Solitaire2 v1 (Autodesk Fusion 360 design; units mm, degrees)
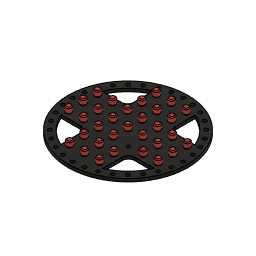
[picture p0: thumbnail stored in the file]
sketch "Esquisse" plane through (0, 0, 0) normal (0, 1, 0) x axis (1, 0, 0)
  line L1 (-45, -34.2237) -> (-77.8058, -34.2237)
  line L2 (-35, -77.4597) -> (-35, -44.2237)
  line L3 (45, -34.2237) -> (77.8058, -34.2237)
  line L4 (35, -77.4597) -> (35, -44.2237)
  line L5 (35, 44.1263) -> (35, 77.4597)
  line L6 (77.8485, 34.1263) -> (45, 34.1263)
  line L7 (-45, 34.1263) -> (-77.8485, 34.1263)
  line L8 (-35, 77.4597) -> (-35, 44.1263)
  circle C1 centre (0, 0) radius 100
  circle C2 centre (0, 0) radius 95
  circle C3 centre (0, 0) radius 89.5
  circle C4 centre (0, 0) radius 85
  circle C5 centre (0, 92.5) radius 3
  circle C6 centre (-18.0459, 90.7226) radius 3
  circle C7 centre (-35.3982, 85.4589) radius 3
  circle C8 centre (-51.3902, 76.9109) radius 3
  circle C9 centre (-65.4074, 65.4074) radius 3
  circle C10 centre (-76.9109, 51.3902) radius 3
  circle C11 centre (-85.4589, 35.3982) radius 3
  circle C12 centre (-90.7226, 18.0459) radius 3
  circle C13 centre (-92.5, 0) radius 3
  circle C14 centre (-90.7226, -18.0459) radius 3
  circle C15 centre (-85.4589, -35.3982) radius 3
  circle C16 centre (-76.9109, -51.3902) radius 3
  circle C17 centre (-65.4074, -65.4074) radius 3
  circle C18 centre (-51.3902, -76.9109) radius 3
  circle C19 centre (-35.3982, -85.4589) radius 3
  circle C20 centre (-18.0459, -90.7226) radius 3
  circle C21 centre (0, -92.5) radius 3
  circle C22 centre (18.0459, -90.7226) radius 3
  circle C23 centre (35.3982, -85.4589) radius 3
  circle C24 centre (51.3902, -76.9109) radius 3
  circle C25 centre (65.4074, -65.4074) radius 3
  circle C26 centre (76.9109, -51.3902) radius 3
  circle C27 centre (85.4589, -35.3982) radius 3
  circle C28 centre (90.7226, -18.0459) radius 3
  circle C29 centre (92.5, 0) radius 3
  circle C30 centre (90.7226, 18.0459) radius 3
  circle C31 centre (85.4589, 35.3982) radius 3
  circle C32 centre (76.9109, 51.3902) radius 3
  circle C33 centre (65.4074, 65.4074) radius 3
  circle C34 centre (51.3902, 76.9109) radius 3
  circle C35 centre (35.3982, 85.4589) radius 3
  circle C36 centre (18.0459, 90.7226) radius 3
  circle C37 centre (-25, 72.4597) radius 2.5
  circle C38 centre (0, 72.4597) radius 2.5
  circle C39 centre (25, 72.4597) radius 2.5
  circle C40 centre (-25, 48.293) radius 2.5
  circle C41 centre (0, 48.293) radius 2.5
  circle C42 centre (25, 48.293) radius 2.5
  circle C43 centre (-25, 24.1263) radius 2.5
  circle C44 centre (0, 24.1263) radius 2.5
  circle C45 centre (25, 24.1263) radius 2.5
  circle C46 centre (-25, -0.0403) radius 2.5
  circle C47 centre (0, -0.0403) radius 2.5
  circle C48 centre (25, -0.0403) radius 2.5
  circle C49 centre (-25, -24.207) radius 2.5
  circle C50 centre (0, -24.207) radius 2.5
  circle C51 centre (25, -24.207) radius 2.5
  circle C52 centre (-25, -48.3737) radius 2.5
  circle C53 centre (0, -48.3737) radius 2.5
  circle C54 centre (25, -48.3737) radius 2.5
  circle C55 centre (-25, -72.5403) radius 2.5
  circle C56 centre (0, -72.5403) radius 2.5
  circle C57 centre (25, -72.5403) radius 2.5
  circle C58 centre (-75, 24.1263) radius 2.5
  circle C59 centre (-50, 24.1263) radius 2.5
  circle C60 centre (-25, 24.1263) radius 2.5
  circle C61 centre (25, 24.1263) radius 2.5
  circle C62 centre (50, 24.1263) radius 2.5
  circle C63 centre (75, 24.1263) radius 2.5
  circle C64 centre (-75, -0.0487) radius 2.5
  circle C65 centre (-50, -0.0487) radius 2.5
  circle C66 centre (-25, -0.0487) radius 2.5
  circle C67 centre (0, -0.0487) radius 2.5
  circle C68 centre (25, -0.0487) radius 2.5
  circle C69 centre (50, -0.0487) radius 2.5
  circle C70 centre (75, -0.0487) radius 2.5
  circle C71 centre (-75, -24.2237) radius 2.5
  circle C72 centre (-50, -24.2237) radius 2.5
  circle C73 centre (-25, -24.2237) radius 2.5
  circle C74 centre (0, -24.2237) radius 2.5
  circle C75 centre (25, -24.2237) radius 2.5
  circle C76 centre (50, -24.2237) radius 2.5
  circle C77 centre (75, -24.2237) radius 2.5
  circle C78 centre (-75, 24.1263) radius 5.0434
  circle C79 centre (-50, 24.1263) radius 5.0434
  circle C80 centre (-25, 24.1263) radius 5.0434
  circle C81 centre (0, 24.1263) radius 5.0434
  circle C82 centre (25, 24.1263) radius 5.0434
  circle C83 centre (50, 24.1263) radius 5.0434
  circle C84 centre (75, 24.1263) radius 5.0434
  circle C85 centre (-75, -0.1237) radius 5.0434
  circle C86 centre (-50, -0.1237) radius 5.0434
  circle C87 centre (-25, -0.1237) radius 5.0434
  circle C88 centre (0, -0.1237) radius 5.0434
  circle C89 centre (25, -0.1237) radius 5.0434
  circle C90 centre (50, -0.1237) radius 5.0434
  circle C91 centre (75, -0.1237) radius 5.0434
  circle C92 centre (-75, -24.3737) radius 5.0434
  circle C93 centre (-50, -24.3737) radius 5.0434
  circle C94 centre (-25, -24.3737) radius 5.0434
  circle C95 centre (0, -24.3737) radius 5.0434
  circle C96 centre (25, -24.3737) radius 5.0434
  circle C97 centre (50, -24.3737) radius 5.0434
  circle C98 centre (75, -24.3737) radius 5.0434
  circle C99 centre (-25, -72.6237) radius 5.0434
  circle C100 centre (0, -72.6237) radius 5.0434
  circle C101 centre (25, -72.6237) radius 5.0434
  circle C102 centre (-25, -48.457) radius 5.0434
  circle C103 centre (0, -48.457) radius 5.0434
  circle C104 centre (25, -48.457) radius 5.0434
  circle C105 centre (-25, -24.2903) radius 5.0434
  circle C106 centre (0, -24.2903) radius 5.0434
  circle C107 centre (25, -24.2903) radius 5.0434
  circle C108 centre (0, -0.1237) radius 5.0434
  circle C109 centre (25, -0.1237) radius 5.0434
  circle C110 centre (-25, 24.043) radius 5.0434
  circle C111 centre (0, 24.043) radius 5.0434
  circle C112 centre (25, 24.043) radius 5.0434
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  point P1 (0, 0)
  point P2 (0, 0)
  point P3 (0, 0)
  point P161 (-77.8058, -34.2237)
  point P162 (-35, -77.4597)
  point P166 (77.8058, -34.2237)
  point P167 (35, -77.4597)
  point P168 (35, 77.4597)
  point P169 (77.8485, 34.1263)
  point P170 (-77.8485, 34.1263)
  point P171 (-35, 77.4597)
  point P40 (25, 72.4597)
  point P38 (-25, 72.4597)
  point P120 (-75, 24.1263)
  point P64 (75, 24.1263)
  point P72 (-75, -24.2237)
  point P78 (75, -24.2237)
  point P143 (25, -72.6737)
  point P56 (-25, -72.5403)
  coincident P1 P2
  coincident P1 P3
  concentric C1 C3
  concentric C3 C4
  tangent C3 C5
  concentric C58 C78
  coincident C4 P161
  horizontal L1
  coincident C4 P162
  perpendicular L1 L2
  coincident C4 P166
  parallel L1 L3
  coincident C4 P167
  perpendicular L1 L4
  coincident C4 P168
  perpendicular L3 L5
  coincident C4 P169
  perpendicular L5 L6
  coincident C4 P170
  parallel L6 L7
  coincident C4 P171
  perpendicular L7 L8
  dimension "d36" diameter C5 = 6
  dimension "d49" radius = 10
  dimension "d50" radius = 10
  dimension "d51" distance P40 L5 = 10
  dimension "d52" distance P38 L8 = 10
  dimension "d53" distance P120 L7 = 10
  dimension "d54" distance P64 L6 = 10
  dimension "d55" distance P72 L1 = 10
  dimension "d56" distance P78 L3 = 10
  dimension "d57" distance P143 L4 = 10
  dimension "d58" distance P56 L2 = 10
  dimension "d4" C-Pattern1-Angle = 360
  dimension "d9" R-Pattern1-uDistance = 50
  dimension "d10" R-Pattern1-vDistance = -145
  dimension "d14" R-Pattern2-uDistance = 75
  dimension "d15" R-Pattern2-vDistance = -48.35
  dimension "d18" R-Pattern3-uDistance = 150
  dimension "d19" R-Pattern3-vDistance = -48.5
  dimension "d22" R-Pattern4-uDistance = 50
  dimension "d23" R-Pattern4-vDistance = 72.5
  dimension "d30" R-Pattern5-uDistance = 150
  dimension "d31" R-Pattern5-vDistance = -48.4
  dimension "d34" R-Pattern6-uDistance = 50
  dimension "d35" R-Pattern6-vDistance = 72.6
extrude "Extrusion1" new body sketch "Esquisse" along normal blind 5 bodies "Plateau"
extrude "Extrusion2" new body sketch "Esquisse" profile of C58 C78 along normal blind 10 bodies "Pion"
move "Déplacer1"
fillet "Congé1" radius 1.5
extrude "Extrusion3" add sketch "Esquisse" profile of C58 along normal blind 5
fillet "Congé2" radius 1.75
fillet "Congé3" radius 1.1
rectangular_pattern "Réseau R" uSpaceDistance 150 vSpaceDistance 48.5 bodies "Pion (1)", "Pion (2)", "Pion (3)", "Pion (4)", "Pion (5)", "Pion (6)", "Pion (7)", "Pion (8)"
copy_paste_bodies "Copier/Coller des corps1"
move "Déplacer2"
copy_paste_bodies "Copier/Coller des corps2"
move "Déplacer3"
copy_paste_bodies "Copier/Coller des corps3"
move "Déplacer4"
copy_paste_bodies "Copier/Coller des corps4"
move "Déplacer5"
copy_paste_bodies "Copier/Coller des corps5"
move "Déplacer6"
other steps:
base_feature "Fonction de base1" bodies "Pion (17)", "Pion (16)", "Pion (18)", "Pion (17) (1)", "Pion (16) (1)", "Pion (18) (1)"
base_feature "Fonction de base2" bodies "Pion (17) (1)", "Pion (17) (1) (1)"
base_feature "Fonction de base3" bodies "Pion (4)", "Pion (3)", "Pion (2)", "Pion (4) (1)", "Pion (3) (1)", "Pion (2) (1)"
base_feature "Fonction de base4" bodies "Pion (4) (1)", "Pion (3) (1)", "Pion (2) (1)", "Pion (4) (1) (1)", "Pion (3) (1) (1)", "Pion (2) (1) (1)"
base_feature "Fonction de base5" bodies "Pion (9)", "Pion (9) (1)"
named bodies: "Plateau", "Pion", "Pion (1)", "Pion (2)", "Pion (3)", "Pion (4)", "Pion (5)", "Pion (6)", "Pion (7)", "Pion (8)", "Pion (9)", "Pion (10)", "Pion (11)", "Pion (12)", "Pion (13)", "Pion (14)", "Pion (15)", "Pion (16)", "Pion (17)", "Pion (18)", "Pion (19)", "Pion (20)", "Pion (17) (1)", "Pion (16) (1)", "Pion (18) (1)", "Pion (17) (1) (1)", "Pion (4) (1)", "Pion (3) (1)", "Pion (2) (1)", "Pion (4) (1) (1)", "Pion (3) (1) (1)", "Pion (2) (1) (1)", "Pion (9) (1)"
